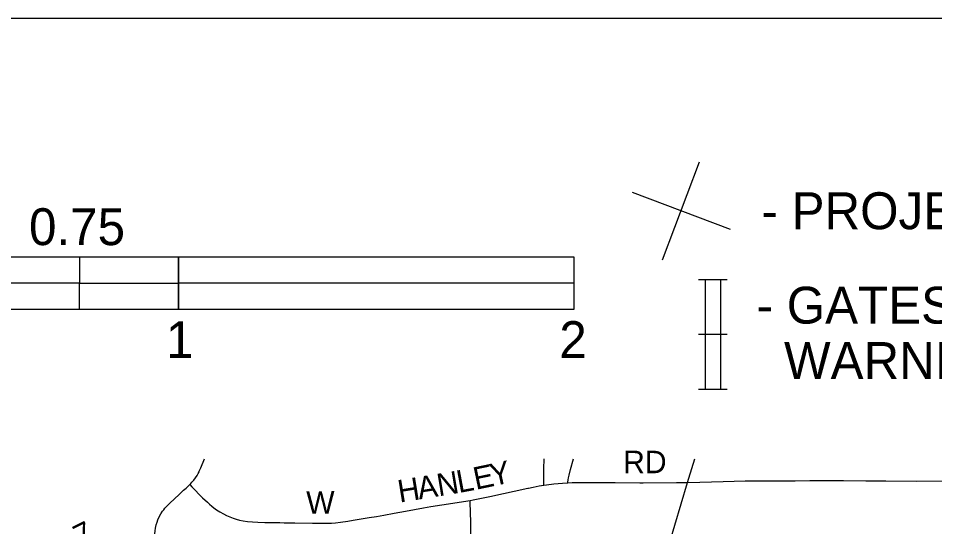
# Model space of a CAD drawing. Extents: x 40529 to 41139, y 15164 to 15584.
# Drawn here: x 40574.5 to 40644, y 15545.7 to 15584.3 of the extents above; entities that cross this region are included whole.
import ezdxf

# ---------------------------------------------------------------- set-up
doc = ezdxf.new("R2010")
doc.units = 0
for name, color, linetype in [('Default', 7, 'Continuous'), ('GM_X_County_Road', 7, 'Continuous'), ('GM_X_County_Road_Text', 7, 'Continuous'), ('GM_X_Township_Road', 7, 'Continuous'), ('GM_X_Township_Road_Text', 7, 'Continuous'), ('GM_X_US_Route', 7, 'Continuous'), ('SC_Scratch1', 7, 'Continuous'), ('SH_Data', 7, 'Continuous'), ('SH_Text', 7, 'Continuous')]:
    doc.layers.add(name, color=color, linetype=linetype)

msp = doc.modelspace()

# ---------------------------------------------------------------- linework, layer by layer
at = {"layer": 'Default'}
for p, q in [((40626.124, 15564.5), (40628.291, 15564.5)), ((40626.624, 15564.5), (40626.624, 15560.334)), ((40627.791, 15564.5), (40627.791, 15560.334)), ((40626.124, 15560.334), (40628.291, 15560.334)), ((40626.624, 15560.334), (40626.624, 15556.167)), ((40627.791, 15560.334), (40627.791, 15556.167)), ((40626.124, 15556.16), (40628.291, 15556.16))]:
    msp.add_line(p, q, dxfattribs=at)
at = {"layer": 'GM_X_County_Road'}
for points in [[(40587.523, 15548.918), (40587.607, 15549.004), (40587.693, 15549.1), (40587.835, 15549.269), (40587.955, 15549.431), (40588.076, 15549.615), (40588.169, 15549.774), (40588.225, 15549.888), (40588.248, 15549.938), (40588.347, 15550.157), (40588.371, 15550.208), (40588.645, 15550.883)], [(40585.55, 15547.013), (40585.644, 15547.127), (40585.812, 15547.317), (40585.999, 15547.503), (40586.718, 15548.179), (40587.052, 15548.488), (40587.249, 15548.658), (40587.452, 15548.846), (40587.523, 15548.918)], [(40587.523, 15548.918), (40587.68, 15548.756), (40588.502, 15547.91), (40588.859, 15547.58), (40589.018, 15547.43), (40589.195, 15547.286), (40589.342, 15547.168), (40589.562, 15547.005), (40589.812, 15546.846), (40590.072, 15546.702), (40590.322, 15546.58), (40590.561, 15546.478), (40590.821, 15546.38), (40591.05, 15546.304), (40591.3, 15546.234), (40591.572, 15546.176), (40591.902, 15546.129), (40592.272, 15546.094), (40592.681, 15546.07), (40593.221, 15546.048), (40593.724, 15546.039), (40594.358, 15546.035), (40594.675, 15546.029), (40595.494, 15546.011), (40596.835, 15545.991), (40597.282, 15545.99), (40597.934, 15545.993), (40598.268, 15546.005), (40598.583, 15546.029), (40598.972, 15546.075), (40599.525, 15546.151), (40599.911, 15546.212), (40601.143, 15546.417), (40601.694, 15546.51), (40602.245, 15546.605), (40603.033, 15546.745), (40603.893, 15546.912), (40605.264, 15547.16), (40605.81, 15547.258), (40606.645, 15547.395), (40608.809, 15547.722)], [(40613.188, 15548.652), (40613.217, 15548.658), (40613.575, 15548.735), (40614.034, 15548.822), (40614.404, 15548.878)], [(40614.404, 15548.878), (40614.588, 15548.907), (40615.145, 15548.974), (40615.797, 15549.031), (40616.217, 15549.054)], [(40616.217, 15549.054), (40616.543, 15549.071), (40617.288, 15549.087), (40619.804, 15549.084), (40621.668, 15549.061), (40621.939, 15549.062)], [(40621.939, 15549.062), (40624.464, 15549.073), (40625.292, 15549.091)], [(40625.292, 15549.091), (40626.223, 15549.11), (40627.992, 15549.162), (40629.667, 15549.202), (40629.727, 15549.202)], [(40629.727, 15549.202), (40632.453, 15549.203), (40633.472, 15549.215), (40634.586, 15549.231), (40635.982, 15549.24), (40637.122, 15549.236), (40638.834, 15549.216), (40640.349, 15549.212), (40642.683, 15549.194), (40644.917, 15549.219), (40646.002, 15549.217)], [(40608.809, 15547.722), (40609.027, 15547.76), (40610.303, 15548.032), (40613.188, 15548.652)], [(40585.377, 15542.831), (40585.183, 15543.422), (40585.071, 15543.759), (40584.995, 15544.028), (40584.931, 15544.321), (40584.89, 15544.561), (40584.868, 15544.786), (40584.862, 15544.992), (40584.87, 15545.198), (40584.893, 15545.423), (40584.927, 15545.626), (40584.98, 15545.864), (40585.038, 15546.062), (40585.111, 15546.256), (40585.213, 15546.477), (40585.329, 15546.692), (40585.456, 15546.899), (40585.55, 15547.013)]]:
    msp.add_lwpolyline(points, dxfattribs=at)
at = {"layer": 'GM_X_Township_Road'}
for points in [[(40614.404, 15548.878), (40614.404, 15548.905), (40614.404, 15549.354), (40614.399, 15550.118), (40614.406, 15550.883)], [(40616.217, 15549.054), (40616.224, 15549.112), (40616.244, 15549.285), (40616.273, 15549.442), (40616.323, 15549.65), (40616.421, 15550.059), (40616.652, 15550.883)], [(40608.902, 15542.832), (40608.9, 15542.884), (40608.88, 15543.763), (40608.842, 15546.082), (40608.812, 15547.564), (40608.809, 15547.722)]]:
    msp.add_lwpolyline(points, dxfattribs=at)
at = {"layer": 'GM_X_US_Route'}
msp.add_lwpolyline([(40620.001, 15526.9), (40620.142, 15527.257), (40620.263, 15527.611), (40620.367, 15527.97), (40620.45, 15528.335), (40620.529, 15528.795), (40620.603, 15529.334), (40620.618, 15529.442), (40620.747, 15530.553), (40620.893, 15531.848), (40621.048, 15533.048), (40621.145, 15533.691), (40621.516, 15535.706), (40621.652, 15536.343), (40621.89, 15537.34), (40622.149, 15538.331), (40622.429, 15539.316), (40623.339, 15542.447), (40623.685, 15543.629), (40624.334, 15545.845), (40625.292, 15549.091), (40625.389, 15549.42), (40625.846, 15550.883)], dxfattribs=at)
at = {"layer": 'SC_Scratch1'}
msp.add_lwpolyline([(40528.651, 15584.313), (41138.651, 15584.313), (41138.651, 15164.313), (40528.651, 15164.313)], close=True, dxfattribs=at)
at = {"layer": 'SH_Data'}
for p, q in [((40623.398, 15565.988), (40626.213, 15573.428)), ((40621.085, 15571.115), (40628.526, 15568.301))]:
    msp.add_line(p, q, dxfattribs=at)
for points in [[(40556.664, 15566.212), (40586.664, 15566.212), (40586.664, 15562.212), (40556.664, 15562.212)], [(40571.664, 15566.212), (40579.164, 15566.212), (40579.164, 15564.212), (40571.664, 15564.212)], [(40586.664, 15566.212), (40616.664, 15566.212), (40616.664, 15562.212), (40586.664, 15562.212)], [(40586.664, 15566.212), (40616.664, 15566.212), (40616.664, 15564.212), (40586.664, 15564.212)], [(40579.164, 15564.212), (40586.664, 15564.212), (40586.664, 15562.212), (40579.164, 15562.212)]]:
    msp.add_lwpolyline(points, close=True, dxfattribs=at)

# ---------------------------------------------------------------- texts
at = {"layer": 'GM_X_County_Road_Text'}
for s, height, rotation, p in [('RD', 1.7063, 0.00188, (40620.409, 15549.788)), ('E', 1.706, 11.80755, (40609.233, 15548.522)), ('Y', 1.706, 12.11831, (40610.492, 15548.786)), ('H', 1.706, 9.20121, (40603.449, 15547.551)), ('A', 1.706, 9.20174, (40604.931, 15547.791)), ('N', 1.706, 9.34524, (40606.417, 15548.031)), ('L', 1.706, 10.49785, (40607.936, 15548.282)), ('W', 1.706, 0.3652, (40596.367, 15546.709))]:
    msp.add_text(s, height=height, rotation=rotation, dxfattribs=at).set_placement(p)
at = {"layer": 'GM_X_Township_Road_Text'}
msp.add_text('7', height=1.706, rotation=26.26506, dxfattribs=at).set_placement((40579.238, 15544.127))
at = {"layer": 'SH_Data'}
for s, p in [('0.75', (40575.327, 15567.099)), ('1', (40585.727, 15558.525)), ('2', (40615.565, 15558.525))]:
    msp.add_text(s, height=2.8, dxfattribs=at).set_placement(p)
at = {"layer": 'SH_Text'}
for s, p in [('  - PROJECT LOCATION', (40628.825, 15568.308)), ('  - GATES, BARRICADES, AND ADVANCE ', (40628.458, 15561.141)), ('    WARNING SIGNS, AS PER MT-101.60', (40628.458, 15556.941))]:
    msp.add_text(s, height=2.8, dxfattribs=at).set_placement(p)

doc.saveas('drawing.dxf')
